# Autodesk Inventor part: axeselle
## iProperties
Shininess: 21.0
Length Units: 11269
Angle Units: 11279
Time Units: 11290
Mass Units: 11283
Length Display Precision: 3
Angle Display Precision: 2
Compacted: True
Created: 2002-01
Part Number: axeselle
Material: Par défaut
Document SubType Name: Modélisation
Designer: pichon
Density: 0.0
Volumn: 0.0
Area: 0.0
PropertySet Name: Model Information
Control State: 0
Master: False
Checked Out: False
Author: pichon
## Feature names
1. Révolution1 [Revolution]
2. Extrusion1
